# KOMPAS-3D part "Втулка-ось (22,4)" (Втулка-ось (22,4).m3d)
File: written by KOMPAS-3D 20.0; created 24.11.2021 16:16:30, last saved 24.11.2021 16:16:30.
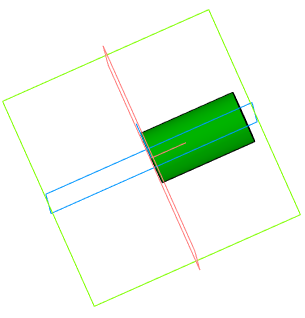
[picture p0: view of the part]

Document properties: Полное имя файла: C:\!WORK!\ЗИГ-18.240.00\Цепь\Втулка-ось (22,4).m3d

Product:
- Part/product: Втулка-ось (22,4)
    Материал: Сталь 45  ГОСТ 1050-2013 (density 7810 kg/m3)
    Масса: 0.0109921

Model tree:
1. Эскиз:1
2. Элемент выдавливания:1  (labels: Сталь 45  ГОСТ 1050-2013)
     Расстояние 1 = 22.4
